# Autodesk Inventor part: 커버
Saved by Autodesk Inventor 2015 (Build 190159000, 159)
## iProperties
Created: 2026-05
Part Number: 커버
Material: 일반
Document SubType Name: Modeling
Designer: 104
Density: 1 g/cm^3
Appearance: 기본값
Author: 104
Author: jhkim
Creation Date: 2026-04-27
Sending System: Autodesk Inventor 2027
Preprocessor: ST-DEVELOPER v20.1
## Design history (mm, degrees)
node "커버1"
node "솔리드1"
node "기준1"
